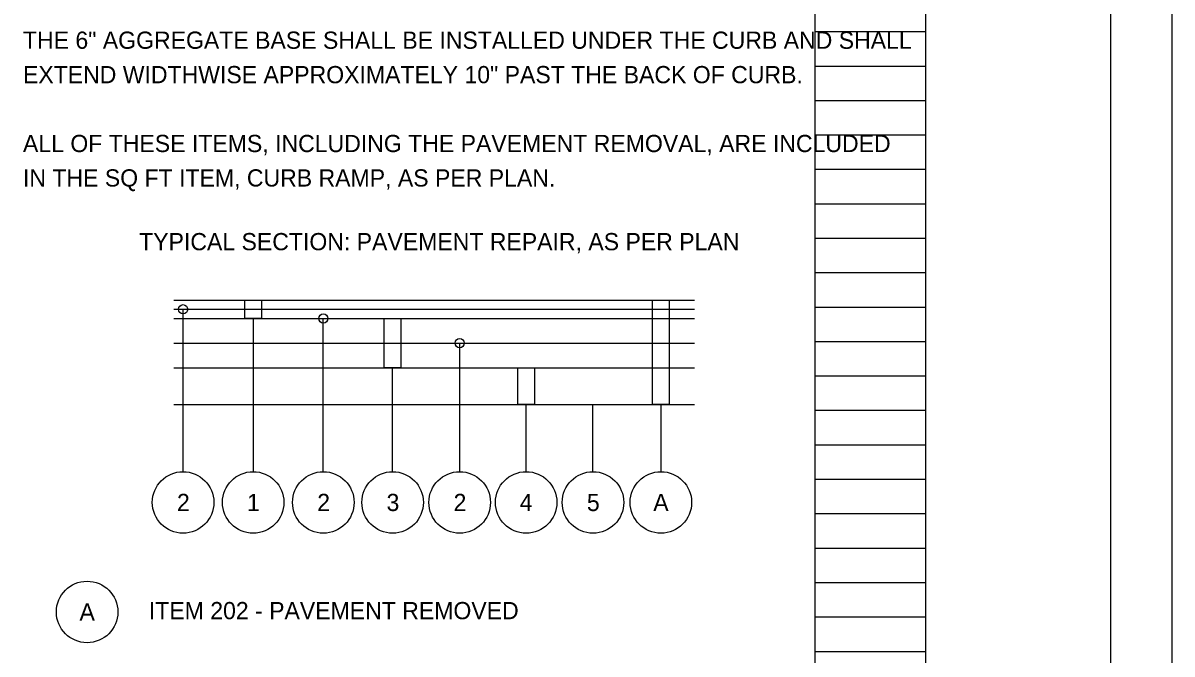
# Model space of a CAD drawing. Extents: x 0 to 34, y 0 to 22.
# Drawn here: x 24.66 to 34, y 6 to 11.13 of the extents above; entities that cross this region are included whole.
import ezdxf

# ---------------------------------------------------------------- set-up
doc = ezdxf.new("R2010")
doc.units = 0
for name, color, linetype in [('SH_Border', 7, 'Continuous'), ('SH_Cut_Line', 7, 'Continuous'), ('SH_Data', 7, 'Continuous'), ('SH_Text', 7, 'Continuous')]:
    doc.layers.add(name, color=color, linetype=linetype)

msp = doc.modelspace()

# ---------------------------------------------------------------- linework, layer by layer
at = {"layer": 'SH_Border'}
msp.add_line((32, 0.5), (32, 21.5), dxfattribs=at)
msp.add_lwpolyline([(1.5, 21.5), (33.5, 21.5), (33.5, 0.5), (1.5, 0.5)], close=True, dxfattribs=at)
at = {"layer": 'SH_Cut_Line'}
msp.add_lwpolyline([(0, 0), (34, 0), (34, 22), (0, 22)], close=True, dxfattribs=at)
at = {"layer": 'SH_Data'}
for p, q in [((31.1, 0.98), (31.1, 21.14)), ((32, 0.98), (32, 21.14)), ((31.1, 11.06), (32, 11.06)), ((31.1, 10.78), (32, 10.78)), ((31.1, 10.5), (32, 10.5)), ((31.1, 10.22), (32, 10.22)), ((31.1, 9.94), (32, 9.94)), ((31.1, 9.66), (32, 9.66)), ((31.1, 9.38), (32, 9.38)), ((31.1, 9.1), (32, 9.1)), ((31.1, 8.82), (32, 8.82)), ((31.1, 8.54), (32, 8.54)), ((31.1, 8.26), (32, 8.26)), ((31.1, 7.98), (32, 7.98)), ((31.1, 7.7), (32, 7.7)), ((31.1, 7.42), (32, 7.42)), ((31.1, 7.14), (32, 7.14)), ((31.1, 6.86), (32, 6.86)), ((31.1, 6.58), (32, 6.58)), ((31.1, 6.3), (32, 6.3)), ((31.1, 6.02), (32, 6.02))]:
    msp.add_line(p, q, dxfattribs=at)
at = {"layer": 'SH_Text'}
for p, q in [((25.8854, 8.8768), (30.1182, 8.8768)), ((25.8854, 8.8018), (30.1182, 8.8018)), ((25.9615, 7.4809), (25.9615, 8.8018)), ((25.8854, 8.7268), (30.1182, 8.7268)), ((26.5313, 8.7268), (26.5313, 7.4809)), ((27.1015, 7.4809), (27.1015, 8.7268)), ((25.8854, 8.5268), (30.1182, 8.5268)), ((28.2098, 7.4809), (28.2098, 8.5268)), ((25.8854, 8.3268), (30.1182, 8.3268)), ((27.6646, 7.4809), (27.6646, 8.3268)), ((25.8854, 8.0268), (30.1182, 8.0268)), ((28.7501, 7.4809), (28.7501, 8.0268)), ((29.2933, 7.4809), (29.2933, 8.0268)), ((29.8453, 8.0268), (29.8453, 7.4809))]:
    msp.add_line(p, q, dxfattribs=at)
for points in [[(26.4638, 8.7268), (26.4638, 8.8768), (26.5988, 8.8768), (26.5988, 8.7268)], [(29.9128, 8.0268), (29.7778, 8.0268), (29.7778, 8.8768), (29.9128, 8.8768)], [(27.5971, 8.7268), (27.7321, 8.7268), (27.7321, 8.3268), (27.5971, 8.3268)], [(28.6826, 8.3268), (28.8176, 8.3268), (28.8176, 8.0268), (28.6826, 8.0268)]]:
    msp.add_lwpolyline(points, close=True, dxfattribs=at)
for centre, radius in [((25.9615, 8.8018), 0.0375), ((27.1015, 8.7268), 0.0375), ((28.2098, 8.5268), 0.0375), ((25.9615, 7.2309), 0.25), ((26.5313, 7.2309), 0.25), ((27.1015, 7.2309), 0.25), ((27.6646, 7.2309), 0.25), ((28.2098, 7.2309), 0.25), ((28.7501, 7.2309), 0.25), ((29.2933, 7.2309), 0.25), ((29.8453, 7.2309), 0.25), ((25.1816, 6.3404), 0.25)]:
    msp.add_circle(centre, radius, dxfattribs=at)

# ---------------------------------------------------------------- texts
for s, p in [('THE 6" AGGREGATE BASE SHALL BE INSTALLED UNDER THE CURB AND SHALL ', (24.66, 10.92)), ('EXTEND WIDTHWISE APPROXIMATELY 10" PAST THE BACK OF CURB.', (24.66, 10.64)), ('ALL OF THESE ITEMS, INCLUDING THE PAVEMENT REMOVAL, ARE INCLUDED', (24.66, 10.08)), ('IN THE SQ FT ITEM, CURB RAMP, AS PER PLAN.', (24.66, 9.8))]:
    msp.add_text(s, height=0.14, dxfattribs=at).set_placement(p)
for s, p in [('TYPICAL SECTION: PAVEMENT REPAIR, AS PER PLAN', (25.6044, 9.2818)), ('2', (25.9118, 7.1609)), ('1', (26.4814, 7.1609)), ('2', (27.0518, 7.1609)), ('3', (27.6154, 7.1609)), ('2', (28.1601, 7.1609)), ('4', (28.6974, 7.1609)), ('5', (29.2439, 7.1609)), ('A', (29.7834, 7.1609)), ('A', (25.1196, 6.2704)), ('ITEM 202 - PAVEMENT REMOVED', (25.6832, 6.2814))]:
    msp.add_text(s, height=0.14, rotation=360, dxfattribs=at).set_placement(p)

doc.saveas('drawing.dxf')
